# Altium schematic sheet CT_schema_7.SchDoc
size 280 x 236 mm
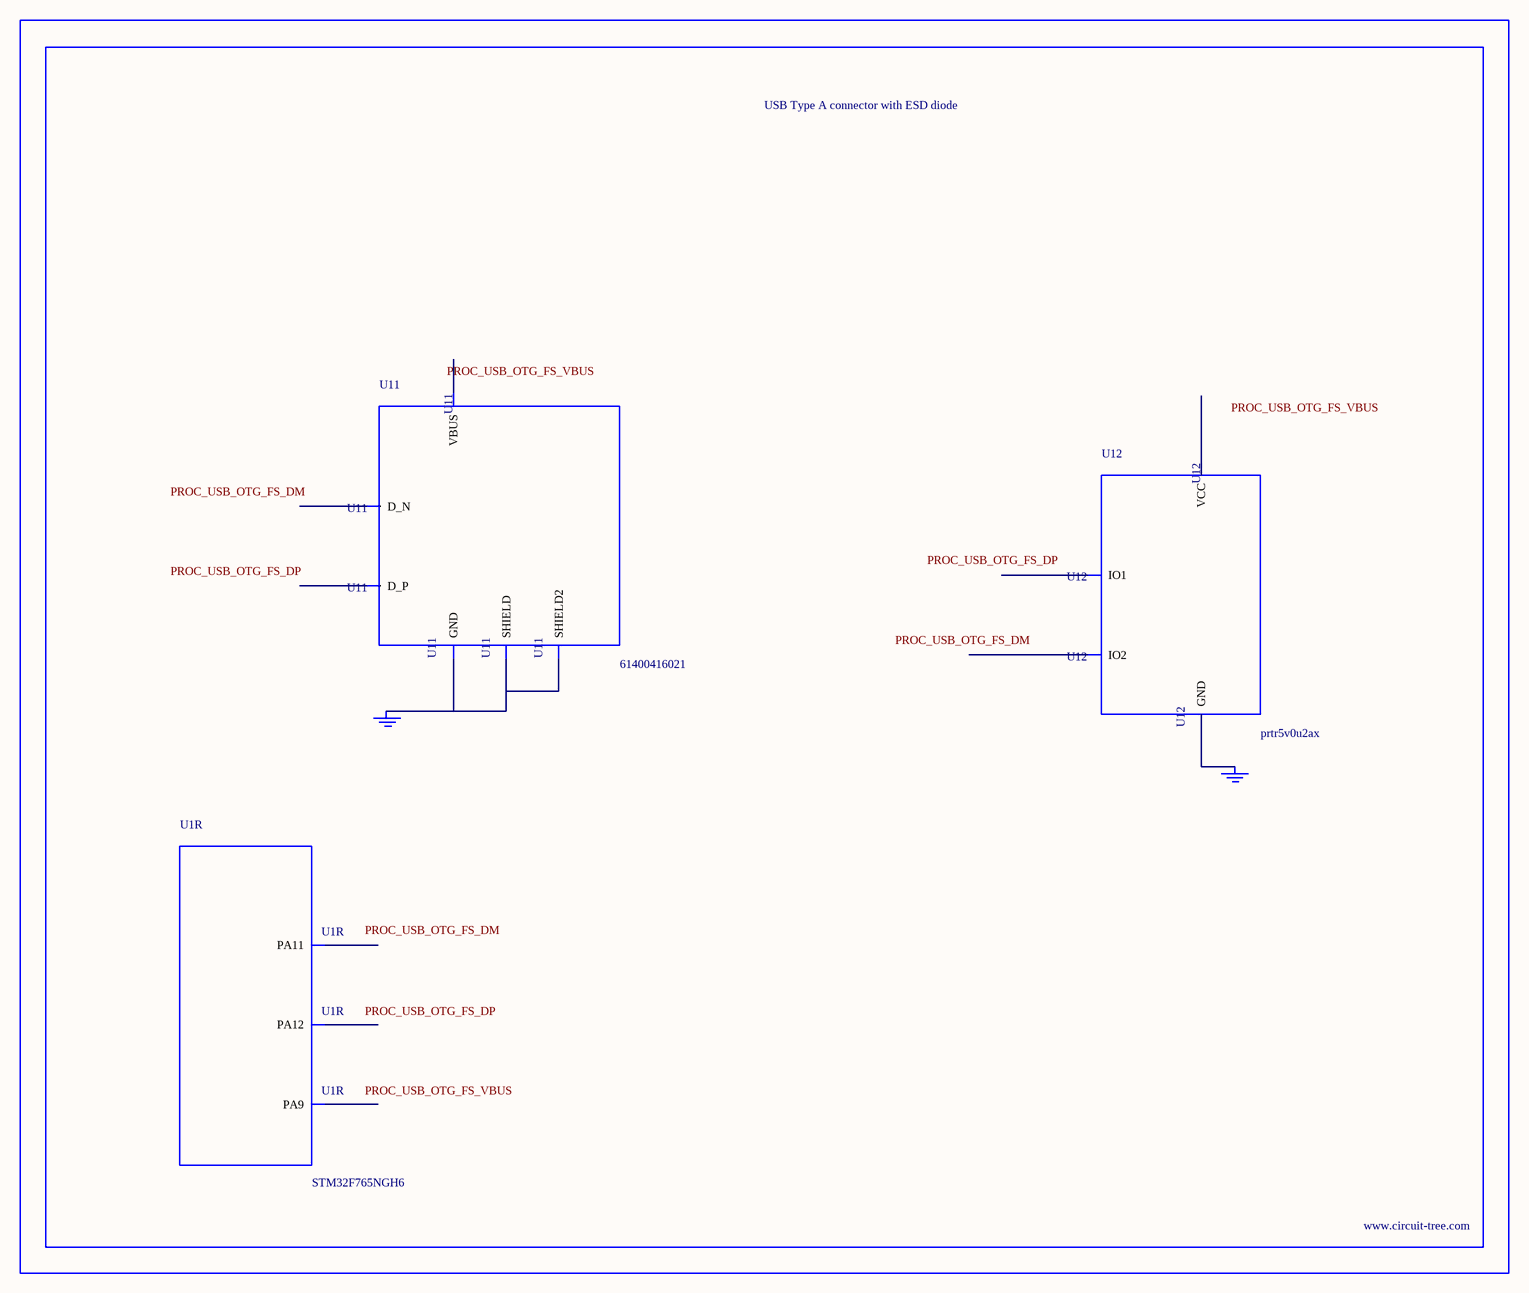
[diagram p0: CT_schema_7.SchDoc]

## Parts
BORDER6  (no value)
GND_INSTANCE_6_0  (no value)
GND_INSTANCE_6_1  (no value)
U1  STM32F765NGH6  [TFBGA216]  (part R of 18)
U11  61400416021  [USB-A-H]
U12  prtr5v0u2ax  [SOT143B]

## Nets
NetGND_INSTANCE_6_0_0: GND_INSTANCE_6_0.0(GND) U11.4(GND) U11.5(SHIELD) U11.6(SHIELD2)
NetGND_INSTANCE_6_1_0: GND_INSTANCE_6_1.0(GND) U12.1(GND)

Not connected (* = marked no-connect by the designer): U1 B15(PA12) C15(PA11) E15(PA9); U11 1(VBUS) 2(D_N) 3(D_P); U12 2(IO1) 3(IO2) 4(VCC)

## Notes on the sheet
- Labels drawn without touching a wire or pin: PROC_USB_OTG_FS_DM, PROC_USB_OTG_FS_DP, PROC_USB_OTG_FS_VBUS

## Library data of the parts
BORDER6 = BORDER_PAGE6
GND_INSTANCE_6_0 GND_INSTANCE_6_1 = GND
